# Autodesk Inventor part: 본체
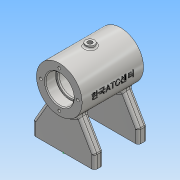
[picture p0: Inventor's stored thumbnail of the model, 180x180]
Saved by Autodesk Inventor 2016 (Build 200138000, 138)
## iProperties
Created: 2018-05
Part Number: 본체
Material: 알루미늄 6061
Document SubType Name: Modeling
Designer: Administrator
Density: 2.7 g/cm^3
Appearance: 알루미늄 - 평지
Mass: 319.522 g
Surface Area: 367.57 cm^2
Volume: 118.341 cm^3
Author: Administrator
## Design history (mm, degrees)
sketch "스케치1"
  geometry: L1 (-35, -20)-(35, -20); L2 (35, 20)-(-35, 20); L3 (-35, -20)-(35, 20); L4 (35, -20)-(-35, 20); L5 (-35, -20)-(-35, -30); L6 (-35, -30)-(35, -30); L7 (35, -30)-(35, -20); L8 (-35, 20)-(-35, 30); L9 (-35, 30)-(35, 30); L10 (35, 30)-(35, 20); 1 further point
  constraints: 20 end point, 4 perpendicular, 2 midpoint, 2 point on line, 1 horizontal, 1 parallel, 1 vertical
  dimensions: "d0" = 70 distance of L2.end L2.start; "d1" = 40 distance of L2.start L1.end; "d2" = 10 distance of L1.start L5.end; "d3" = 10 distance of L2.end L8.end
extrude "돌출1" new body sketch "스케치1" distance "d4" = 15; taper "d5" = 0 deg
sketch "스케치2"
  geometry: 1 further point
sketch "스케치3"
  geometry: L1 (0, -15)-(70, -15) reference; L2 (70, -15)-(35, -75.622); L3 (70, -15)-(130.842, -15); L4 (0, 0)-(0, -15) reference; L5 (0, -15)-(35, -75.622); L6 (0, -15)-(76.56, -15); 1 further point
  constraints: 8 end point, 2 horizontal
  dimensions: "d6" = 120 deg angle of L2 L3; "d7" = 60 deg angle of L5 L6
extrude "돌출2" join sketch "스케치3" distance "d8" = 10; taper "d9" = 0 deg
sketch "스케치4"
  geometry: L1 (0, 0)-(0, 15) reference; L2 (0, 15)-(35, 75.622); L3 (70, 15)-(35, 75.622) reference; L4 (35, 75.622)-(70, 15); L5 (70, 15)-(0, 15); 1 further point
  constraints: 6 end point, 1 collinear, 1 perpendicular
extrude "돌출3" join sketch "스케치4" distance "d10" = 10; taper "d11" = 0 deg
sketch "스케치5"
  geometry: L1 (-30, 75.622)-(-30, 15) reference; L2 (30, 15)-(30, 75.622) reference; L3 (-35, 65)-(35, 65); L4 (0, 0)-(0, 65); L5 (-35, 65)-(-35, 91); L6 (-35, 91)-(35, 91); L7 (35, 91)-(35, 65)
  constraints: 10 end point, 2 horizontal, 2 vertical, 1 midpoint, 1 perpendicular
  dimensions: "d12" = 70 distance of L3.start L3.end; "d13" = 65 distance of L4.end L4.start; "d15" = 52 diameter of L6 L3
revolve "회전1" sketch "스케치5" stored, may be unused: angle "d16" = 90 deg
sketch "스케치6"
  geometry: L1 (0, 0)-(0, 65); L2 (-35, 65)-(35, 65); L3 (-35, 65)-(-35, 81); L4 (-35, 39)-(-35, 91) reference; L5 (-35, 81)-(-23, 81); L6 (-23, 81)-(-23, 79); L7 (-23, 79)-(-21, 79); L8 (-21, 79)-(-21, 86); L9 (-21, 86)-(21, 86); L10 (21, 86)-(21, 79); L11 (21, 79)-(23, 79); L12 (23, 79)-(23, 81); L13 (23, 81)-(35, 81); L14 (35, 81)-(35, 65); L15 (35, 39)-(35, 91) reference
  constraints: 26 end point, 6 perpendicular, 5 point on line, 2 horizontal, 1 collinear, 1 midpoint, 1 vertical
  dimensions: "d17" = 65 distance of L1.end L1.start; "d18" = 70 distance of L2.start L2.end; "d19" = 32 diameter of L5 L2; "d20" = 28 diameter of L7 L2; "d21" = 42 diameter of L9 L2; "d22" = 12 distance of L3.end L5.end; "d23" = 2 distance of L6.end L7.end; "d24" = 2 distance of L10.end L11.end; "d25" = 12 distance of L12.end L13.end
revolve "회전2" sketch "스케치6" stored, may be unused: angle "d26" = 90 deg
node "작업 평면1"
sketch "스케치7"
  geometry: C1 r 5 at (0, 0); 1 further point
  constraints: 1 centre point, 1 coincident
  dimensions: "d28" = 10 diameter of C1
extrude "돌출4" join sketch "스케치7" stored distance "d29" = 10; taper "d30" = 0 deg
sketch "스케치8"
  geometry: L1 (0, 0)-(0, -25); L2 (0, -25)-(20, -25); L3 (20, -25)-(20, 25); L4 (20, 25)-(-20, 25); L5 (-20, 25)-(-20, -25); L6 (-20, -25)-(0, -25); 4 further points
  constraints: 12 end point, 4 coincident, 4 perpendicular, 1 point on line, 1 vertical
  dimensions: "d34" = 25 distance of L1.start L1.end; "d35" = 20 distance of L1.end L2.end; "d36" = 50 distance of L2.end L3.end; "d37" = 40 distance of L3.end L4.end; "d38" = 50 distance of L4.end L5.end; "d39" = 20 distance of L5.end L1.end (derived)
hole "구멍1" sketch "스케치8" at (-20, -25), (20, -25), (20, 25), (-20, 25) diameter "d40" = 4.134; stored, may be unused: countersink angle "d44" = 90 deg, drill point angle "d46" = 118 deg; dims "d41" = 8, "d42" = 4, "d43" = 2, "d45" = 12.2
hole "구멍2" diameter "d49" = 5.188; stored, may be unused: countersink angle "d53" = 90 deg, drill point angle "d55" = 0 deg; dims "d47" = 10, "d48" = 10, "d50" = 12, "d51" = 4, "d52" = 2, "d54" = 16
sketch "스케치9"
  geometry: L1 (0, 65)-(9.919, 37.749); L2 (0, 65)-(29, 65); L3 (15.557, 39.801)-(9.919, 37.749); L4 (14.063, 43.905)-(15.557, 39.801); L5 (8.425, 41.853)-(9.919, 37.749); L6 (8.425, 41.853)-(14.063, 43.905); C1 r 14 at (0, 65) reference; 1 further point
  constraints: 12 end point, 1 collinear, 1 equal length, 1 horizontal, 1 perpendicular
  dimensions: "d56" = 29 distance of L1.end L1.start; "d57" = 70 deg angle of L1 L2; "d59" = 90 deg angle of L3 L1
revolve "회전3" sketch "스케치9" stored, may be unused: angle "d60" = 90 deg
hole "구멍3" diameter "d63" = 5.188; stored, may be unused: countersink angle "d67" = 90 deg, drill point angle "d69" = 0 deg; dims "d61" = 10, "d62" = 10, "d64" = 12, "d65" = 4, "d66" = 2, "d68" = 16
fillet "모깎기1" dims "d70" = 2
fillet "모깎기2" dims "d71" = 2
fillet "모깎기3" dims "d72" = 3
fillet "모깎기4" dims "d73" = 3
chamfer "모따기1" distance "d74" = 1; stored, may be unused: second distance "d75" = 2, angle "d76" = 45 deg
fillet "모깎기6" dims "d78" = 3
fillet "모깎기7" dims "d79" = 0.3
node "작업 평면2"
sketch "스케치12"
  geometry: 3 further points
  constraints: 1 coincident, 2 other
feature "엠보싱1" sketch "스케치12" dims "d6" = 120 deg, "d7" = 60 deg, "d82" = 0.5, "d83" = 0
sketch "스케치13" dims "d84" = 42
  geometry: L1 (0, 0)-(0, 21); 2 further points
  constraints: 2 end point, 1 coincident, 1 vertical, 1 vertical alignment, 2 other
hole "구멍4" sketch "스케치13" at (0, 21) diameter "d85" = 3.242; stored, may be unused: countersink angle "d89" = 90 deg, drill point angle "d91" = 118 deg; dims "d86" = 8, "d87" = 4, "d88" = 2, "d90" = 10
node "솔리드1"
pattern_circular "원형 패턴1" dims angle "d93" = 360 deg
mirror "대칭1"
other parameters: "d27" = 94
